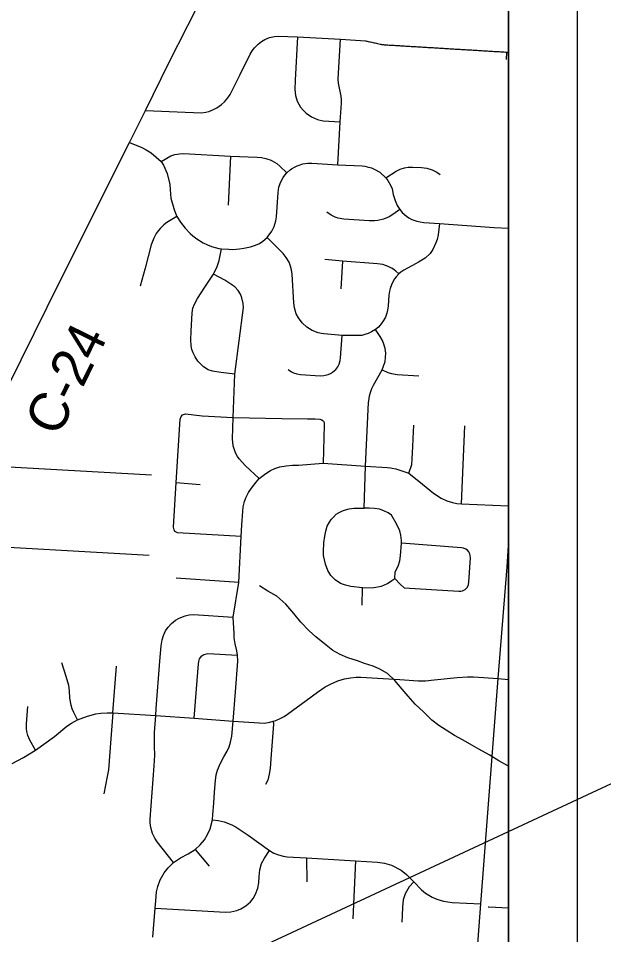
# Model space of a CAD drawing. Extents: x 0 to 34, y 0 to 22.
# Drawn here: x 9.603 to 10.457, y 8.278 to 9.615 of the extents above; entities that cross this region are included whole.
import ezdxf

# ---------------------------------------------------------------- set-up
doc = ezdxf.new("R2010")
doc.units = 0
for name, color, linetype in [('GM_X_Corporation', 7, 'Continuous'), ('GM_X_County_Road', 7, 'Continuous'), ('GM_X_County_Road_Text', 7, 'Continuous'), ('GM_X_Minor_River', 7, 'Continuous'), ('GM_X_Township_Road', 7, 'Continuous'), ('SH_Data', 7, 'Continuous'), ('SH_Text', 7, 'Continuous')]:
    doc.layers.add(name, color=color, linetype=linetype)

msp = doc.modelspace()

# ---------------------------------------------------------------- linework, layer by layer
at = {"layer": 'GM_X_Corporation'}
for points in [[(10.3182, 6.9963), (10.3182, 10.1841), (3.5182, 10.1841)], [(10.3182, 6.9963), (10.3182, 10.1841), (8.0168, 10.1841), (8.012, 10.1113), (7.9906, 9.8037), (7.9854, 9.7171), (7.9173, 8.8475), (7.9043, 8.6471), (7.8824, 8.2446), (7.8769, 8.1664), (7.8619, 7.9568), (7.8248, 7.359), (7.8118, 7.1421)]]:
    msp.add_lwpolyline(points, dxfattribs=at)
at = {"layer": 'GM_X_County_Road'}
for points in [[(9.2983, 8.492), (9.3206, 8.5378), (9.4763, 8.8512), (9.532, 8.9642), (9.6643, 9.2319), (9.7654, 9.4338), (9.7887, 9.4806), (9.823, 9.5499), (9.8784, 9.6595), (9.9012, 9.7059), (9.9498, 9.7963), (10.0655, 10.0271), (10.1462, 10.1841)], [(10.2498, 7.9432), (10.2722, 8.252), (10.2775, 8.3232), (10.3028, 8.6518), (10.3159, 8.8149), (10.3182, 8.8454)], [(10.2884, 8.3191), (10.2894, 8.3191), (10.3182, 8.3175)]]:
    msp.add_lwpolyline(points, dxfattribs=at)
at = {"layer": 'GM_X_Minor_River'}
msp.add_lwpolyline([(10.3182, 8.5241), (10.3181, 8.5242), (10.3037, 8.5321), (10.2897, 8.5408), (10.2749, 8.5488), (10.2643, 8.5548), (10.2518, 8.562), (10.2393, 8.5688), (10.2272, 8.5764), (10.2162, 8.5835), (10.206, 8.5911), (10.1939, 8.6036), (10.1821, 8.6146), (10.1715, 8.6263), (10.1628, 8.6362), (10.1522, 8.649), (10.1416, 8.6593), (10.1306, 8.6657), (10.1208, 8.6702), (10.1083, 8.674), (10.098, 8.6778), (10.084, 8.6823), (10.0727, 8.6872), (10.0621, 8.6929), (10.0522, 8.7004), (10.0371, 8.7129), (10.0272, 8.7213), (10.0155, 8.7341), (10.0053, 8.7466), (9.9935, 8.7606), (9.9803, 8.772), (9.9674, 8.7792), (9.9549, 8.7871)], dxfattribs=at)
at = {"layer": 'GM_X_Township_Road'}
for p, q in [((10.3149, 9.5549), (10.3156, 9.5656)), ((9.9129, 9.4136), (9.9094, 9.3422)), ((10.076, 9.2606), (10.0737, 9.2205)), ((10.2494, 8.9069), (10.2542, 9.0203)), ((9.532, 8.9642), (9.7974, 8.9489)), ((9.8335, 8.9377), (9.8683, 8.935)), ((9.9249, 8.7921), (9.8337, 8.7982)), ((10.1046, 8.7587), (10.1054, 8.7841)), ((9.7414, 8.6018), (9.7468, 8.6699)), ((10.3028, 8.6518), (10.3182, 8.6506)), ((9.8611, 8.4027), (9.8816, 8.3783)), ((10.0233, 8.3902), (10.0239, 8.3552)), ((10.0952, 8.3861), (10.0909, 8.3015))]:
    msp.add_line(p, q, dxfattribs=at)
for points in [[(9.7887, 9.4806), (9.8467, 9.4779), (9.8589, 9.4773), (9.8706, 9.4772), (9.877, 9.4782), (9.881, 9.4792), (9.888, 9.4818), (9.8929, 9.4843), (9.8997, 9.4891), (9.9038, 9.4929), (9.9089, 9.4989), (9.9122, 9.504), (9.916, 9.5114), (9.9262, 9.5318), (9.9416, 9.5626), (9.9443, 9.5673), (9.9475, 9.5717), (9.9509, 9.5754), (9.953, 9.5773), (9.958, 9.5811), (9.9626, 9.5838), (9.9695, 9.5867), (9.9768, 9.5884), (9.9822, 9.589), (10.0104, 9.5877), (10.0729, 9.5843), (10.1094, 9.5819), (10.111, 9.5817), (10.1119, 9.5815), (10.1136, 9.5811), (10.1153, 9.5807), (10.117, 9.5804), (10.1187, 9.58), (10.1204, 9.5796), (10.1221, 9.5792), (10.1238, 9.5789), (10.1255, 9.5785), (10.1272, 9.5781), (10.1289, 9.5777), (10.1307, 9.5773), (10.1314, 9.5772), (10.1321, 9.577), (10.1329, 9.5769), (10.1336, 9.5768), (10.1343, 9.5767), (10.1351, 9.5766), (10.1358, 9.5765), (10.1366, 9.5764), (10.1373, 9.5763), (10.1381, 9.5763), (10.14, 9.5762), (10.1419, 9.5761), (10.1438, 9.5759), (10.1456, 9.5758), (10.1475, 9.5757), (10.1494, 9.5756), (10.1513, 9.5755), (10.1532, 9.5754), (10.1551, 9.5753), (10.157, 9.5752), (10.1589, 9.575), (10.1608, 9.5749), (10.1626, 9.5748), (10.1645, 9.5747), (10.1664, 9.5746), (10.1683, 9.5745), (10.1702, 9.5744), (10.1721, 9.5742), (10.174, 9.5741), (10.1759, 9.574), (10.1778, 9.5739), (10.1796, 9.5738), (10.1815, 9.5737), (10.1834, 9.5736), (10.1853, 9.5734), (10.1872, 9.5733), (10.1891, 9.5732), (10.191, 9.5731), (10.1929, 9.573), (10.1948, 9.5729), (10.1966, 9.5728), (10.1985, 9.5726), (10.2004, 9.5725), (10.2023, 9.5724), (10.2042, 9.5723), (10.2061, 9.5722), (10.208, 9.5721), (10.2099, 9.572), (10.2118, 9.5718), (10.2136, 9.5717), (10.2155, 9.5716), (10.2174, 9.5715), (10.2193, 9.5714), (10.2212, 9.5713), (10.2231, 9.5712), (10.225, 9.5711), (10.2269, 9.5709), (10.2288, 9.5708), (10.2306, 9.5707), (10.2325, 9.5706), (10.2344, 9.5705), (10.2363, 9.5704), (10.2382, 9.5703), (10.2401, 9.5701), (10.242, 9.57), (10.2439, 9.5699), (10.2458, 9.5698), (10.2476, 9.5697), (10.2495, 9.5696), (10.2514, 9.5695), (10.2533, 9.5693), (10.2552, 9.5692), (10.2571, 9.5691), (10.259, 9.569), (10.2609, 9.5689), (10.2627, 9.5688), (10.2646, 9.5687), (10.2665, 9.5685), (10.2684, 9.5684), (10.2703, 9.5683), (10.2722, 9.5682), (10.2741, 9.5681), (10.276, 9.568), (10.2779, 9.5679), (10.2798, 9.5677), (10.2816, 9.5676), (10.2835, 9.5675), (10.2854, 9.5674), (10.2873, 9.5673), (10.2892, 9.5672), (10.2911, 9.5671), (10.293, 9.567), (10.2949, 9.5668), (10.2968, 9.5667), (10.2986, 9.5666), (10.3005, 9.5665), (10.3024, 9.5664), (10.3043, 9.5663), (10.3062, 9.5662), (10.3081, 9.566), (10.31, 9.5659), (10.3119, 9.5658), (10.3138, 9.5657), (10.3156, 9.5656), (10.3166, 9.5655), (10.3176, 9.5655), (10.3182, 9.5655)], [(10.0104, 9.5877), (10.0068, 9.5249), (10.0063, 9.511), (10.0074, 9.5023), (10.0101, 9.494), (10.015, 9.4853), (10.0186, 9.4808), (10.0231, 9.4764), (10.031, 9.471), (10.0394, 9.4674), (10.0476, 9.4656), (10.0727, 9.4638)], [(10.069, 9.4013), (10.0727, 9.4638), (10.0745, 9.4911), (10.0746, 9.4962), (10.0741, 9.5014), (10.0733, 9.506), (10.0711, 9.5153), (10.0701, 9.5205), (10.0697, 9.5256), (10.0701, 9.5347), (10.0729, 9.5843)], [(9.7654, 9.4338), (9.7834, 9.4265), (9.79, 9.4233), (9.797, 9.4187), (9.8119, 9.4061), (9.8153, 9.4006), (9.8206, 9.3885), (9.8241, 9.3724), (9.8253, 9.3583), (9.826, 9.3524), (9.8302, 9.3375), (9.8318, 9.3331), (9.8344, 9.3258), (9.84, 9.3175), (9.8465, 9.3089), (9.854, 9.301), (9.8578, 9.2977), (9.8637, 9.2932), (9.873, 9.2875), (9.8792, 9.2845), (9.8852, 9.2822), (9.8957, 9.2792), (9.8996, 9.2785), (9.9103, 9.278), (9.915, 9.2779), (9.9212, 9.2782), (9.9258, 9.2787), (9.932, 9.2798), (9.9419, 9.2818), (9.949, 9.2839), (9.9551, 9.2866), (9.96, 9.2897), (9.9663, 9.2951), (9.9729, 9.3044), (9.9762, 9.311), (9.9776, 9.3148), (9.9789, 9.3196), (9.9797, 9.3255), (9.9822, 9.3608), (9.9834, 9.3686), (9.9851, 9.374), (9.9871, 9.3785), (9.9896, 9.3828), (9.992, 9.3861), (9.9949, 9.3896), (9.9998, 9.3938), (10.0018, 9.3952), (10.0068, 9.3982), (10.0098, 9.3996), (10.0128, 9.4008), (10.0184, 9.4024), (10.0216, 9.403), (10.0257, 9.4035), (10.0282, 9.4036), (10.0315, 9.4035), (10.069, 9.4013), (10.1048, 9.3995), (10.1088, 9.3991), (10.1121, 9.3985), (10.1185, 9.3967), (10.1223, 9.3951), (10.1302, 9.3906), (10.1393, 9.382), (10.142, 9.3785), (10.1464, 9.3706), (10.1482, 9.366), (10.1501, 9.358), (10.1527, 9.3493), (10.1558, 9.3417), (10.1594, 9.3359), (10.1632, 9.3317), (10.1694, 9.3264), (10.1729, 9.324), (10.1773, 9.3216), (10.1842, 9.319), (10.189, 9.3179), (10.1945, 9.3172), (10.2172, 9.3154), (10.2971, 9.31), (10.3182, 9.3088)], [(9.8119, 9.4061), (9.8256, 9.4143), (9.8317, 9.4162), (9.8386, 9.4173), (9.8441, 9.4175), (9.9129, 9.4136), (9.9518, 9.4122), (9.9578, 9.4118), (9.9643, 9.4106), (9.9674, 9.4096), (9.9705, 9.4085), (9.9735, 9.4071), (9.9771, 9.4052), (9.9805, 9.4029), (9.9849, 9.3992), (9.9949, 9.3896)], [(10.1393, 9.382), (10.1543, 9.392), (10.1603, 9.3948), (10.1666, 9.3968), (10.1715, 9.3976), (10.1781, 9.398), (10.1914, 9.3972), (10.1988, 9.3962), (10.2067, 9.3937), (10.2134, 9.3904), (10.2182, 9.387)], [(10.1594, 9.3359), (10.1496, 9.3287), (10.1438, 9.3253), (10.1359, 9.322), (10.1275, 9.3199), (10.1228, 9.3194), (10.1151, 9.3193), (10.078, 9.3219), (10.0699, 9.3234), (10.0653, 9.325), (10.0594, 9.3279), (10.0533, 9.3321)], [(9.8344, 9.3258), (9.8199, 9.317), (9.8155, 9.3136), (9.81, 9.3083), (9.8057, 9.303), (9.8045, 9.3009), (9.8008, 9.2942), (9.7989, 9.2895), (9.7973, 9.2845), (9.7882, 9.2504), (9.7813, 9.2241)], [(10.2172, 9.3154), (10.2153, 9.2991), (10.2138, 9.2922), (10.2122, 9.2875), (10.2077, 9.2779), (10.2038, 9.2721), (10.1965, 9.2651), (10.1867, 9.259), (10.1832, 9.2572), (10.1709, 9.2505), (10.1655, 9.2474), (10.1612, 9.2446), (10.1579, 9.242), (10.154, 9.2377), (10.152, 9.235), (10.1498, 9.2315), (10.1472, 9.2264), (10.1453, 9.2209), (10.1443, 9.2169), (10.1436, 9.2111), (10.1425, 9.1951), (10.1417, 9.1894), (10.1405, 9.1846), (10.1385, 9.1792), (10.1359, 9.1741), (10.1326, 9.1694), (10.1283, 9.1646), (10.1241, 9.161), (10.1185, 9.1574), (10.1134, 9.155), (10.1088, 9.1535), (10.104, 9.1524), (10.0756, 9.1522), (10.049, 9.1547), (10.0452, 9.1552), (10.0404, 9.1563), (10.0318, 9.1596), (10.024, 9.1644), (10.0172, 9.1707), (10.0118, 9.178), (10.0087, 9.1839), (10.0059, 9.1926), (10.0049, 9.1999), (10.0026, 9.2416), (10.0018, 9.2479), (10.0003, 9.2535), (9.9981, 9.2591), (9.9941, 9.266), (9.9893, 9.2718), (9.9663, 9.2951)], [(9.919, 9.0958), (9.8985, 9.0984), (9.8866, 9.1), (9.8803, 9.1022), (9.8732, 9.1066), (9.8653, 9.1148), (9.8611, 9.1213), (9.8582, 9.1272), (9.8562, 9.1316), (9.8552, 9.1374), (9.8547, 9.1461), (9.8554, 9.1587), (9.8568, 9.1854), (9.8579, 9.1922), (9.8601, 9.1982), (9.8648, 9.206), (9.8755, 9.2227), (9.8878, 9.2419), (9.8932, 9.2531), (9.896, 9.2615), (9.8996, 9.2785)], [(10.1579, 9.242), (10.1538, 9.2459), (10.1512, 9.248), (10.1478, 9.2503), (10.1463, 9.2511), (10.1427, 9.253), (10.1388, 9.2545), (10.1349, 9.2557), (10.1309, 9.2565), (10.1268, 9.257), (10.076, 9.2606), (10.0502, 9.263)], [(9.9547, 8.9439), (9.9347, 8.9624), (9.9256, 8.9722), (9.9229, 8.9756), (9.9198, 8.981), (9.9168, 8.9915), (9.9159, 9.0014), (9.9164, 9.0327), (9.919, 9.0958), (9.9316, 9.193), (9.931, 9.1991), (9.9292, 9.2073), (9.9274, 9.2127), (9.924, 9.2178), (9.9192, 9.2232), (9.9046, 9.2329), (9.8878, 9.2419)], [(10.1076, 8.9006), (10.1094, 8.9617), (10.1141, 9.0543), (10.1148, 9.06), (10.1155, 9.0641), (10.1169, 9.0692), (10.119, 9.075), (10.1213, 9.08), (10.1337, 9.1024), (10.136, 9.1075), (10.1381, 9.1145), (10.1389, 9.1202), (10.139, 9.1267), (10.1382, 9.1332), (10.1365, 9.1395), (10.1343, 9.1449), (10.131, 9.1506), (10.1241, 9.161)], [(9.9967, 9.1027), (10.0017, 9.0993), (10.0048, 9.0979), (10.0095, 9.0964), (10.0149, 9.0955), (10.0433, 9.0936), (10.0488, 9.0938), (10.0551, 9.0953), (10.0583, 9.0967), (10.0616, 9.0988), (10.0661, 9.1027), (10.0691, 9.1066), (10.0711, 9.1105), (10.0727, 9.1157), (10.0733, 9.1195), (10.0756, 9.1522)], [(10.1337, 9.1024), (10.1421, 9.0983), (10.1476, 9.0966), (10.1556, 9.0954), (10.1871, 9.0933)], [(9.9284, 8.8593), (9.8357, 8.8645), (9.8337, 8.8653), (9.8318, 8.8665), (9.8304, 8.869), (9.8299, 8.8726), (9.8335, 8.9377), (9.8396, 9.0301), (9.8408, 9.0341), (9.8428, 9.0364), (9.847, 9.0378), (9.8715, 9.0351), (9.9164, 9.0327)], [(9.9164, 9.0327), (9.9876, 9.0312), (10.025, 9.0309), (10.0362, 9.0307), (10.0428, 9.0301), (10.0461, 9.0292), (10.0484, 9.0272), (10.0491, 9.0252), (10.0492, 9.0213), (10.048, 8.9659)], [(10.1726, 8.9515), (10.177, 8.9642), (10.1777, 8.972), (10.1781, 8.982), (10.1787, 8.9892), (10.179, 9.002), (10.1798, 9.0213)], [(9.7996, 8.2748), (9.8029, 8.3168), (9.8038, 8.3277), (9.805, 8.341), (9.8066, 8.3484), (9.8104, 8.3585), (9.816, 8.3684), (9.8219, 8.3759), (9.8299, 8.3836), (9.84, 8.3905), (9.8509, 8.3962), (9.8611, 8.4027), (9.8683, 8.4092), (9.8747, 8.4169), (9.8794, 8.4245), (9.883, 8.4326), (9.8864, 8.4458), (9.887, 8.4538), (9.8883, 8.4703), (9.8894, 8.4861), (9.8907, 8.503), (9.8919, 8.5117), (9.8936, 8.5181), (9.8976, 8.5275), (9.9032, 8.5378), (9.908, 8.5462), (9.9107, 8.5525), (9.9128, 8.5592), (9.9146, 8.5677), (9.9164, 8.5899), (9.9198, 8.6324), (9.9233, 8.6774), (9.9231, 8.6861), (9.9222, 8.6924), (9.9197, 8.7026), (9.9183, 8.7111), (9.9183, 8.7178), (9.9165, 8.7414), (9.9249, 8.7921), (9.9284, 8.8593), (9.9293, 8.8759), (9.9307, 8.8957), (9.9314, 8.9025), (9.9333, 8.9102), (9.9351, 8.9153), (9.939, 8.9233), (9.9432, 8.9297), (9.9484, 8.9361), (9.9547, 8.9439), (9.9641, 8.9512), (9.9709, 8.9554), (9.9774, 8.9584), (9.9849, 8.9606), (9.994, 8.962), (10.0029, 8.9629), (10.012, 8.963), (10.048, 8.9659), (10.1094, 8.9617), (10.1409, 8.9596), (10.1458, 8.9591), (10.1484, 8.9587), (10.1537, 8.9576), (10.1626, 8.9549), (10.1726, 8.9515), (10.1928, 8.9354), (10.2087, 8.9223), (10.2196, 8.9151), (10.2279, 8.9113), (10.2365, 8.9086), (10.2428, 8.9073), (10.2494, 8.9069), (10.3182, 8.9036)], [(10.1054, 8.7841), (10.0883, 8.786), (10.0804, 8.7879), (10.073, 8.7907), (10.0651, 8.7961), (10.0592, 8.8024), (10.0545, 8.8094), (10.051, 8.8186), (10.0496, 8.8249), (10.0485, 8.8315), (10.0483, 8.8372), (10.0488, 8.8497), (10.0502, 8.8595), (10.0515, 8.8671), (10.0539, 8.8743), (10.057, 8.8799), (10.0596, 8.8841), (10.0627, 8.8875), (10.0669, 8.8915), (10.0711, 8.8943), (10.0758, 8.8966), (10.0802, 8.8981), (10.0858, 8.8993), (10.0925, 8.9005), (10.1076, 8.9006)], [(10.1054, 8.7841), (10.1215, 8.7847), (10.1328, 8.7868), (10.1414, 8.7905), (10.1479, 8.7947), (10.1523, 8.7979), (10.1528, 8.8077), (10.1571, 8.8156), (10.1596, 8.8234), (10.1606, 8.8307), (10.1618, 8.8494), (10.1619, 8.8535), (10.1611, 8.8608), (10.1595, 8.8672), (10.1545, 8.8776), (10.1472, 8.8903), (10.1428, 8.8938), (10.1363, 8.8966), (10.1298, 8.8989), (10.1228, 8.9), (10.115, 8.9005), (10.1076, 8.9006)], [(9.4763, 8.8512), (9.4863, 8.8499), (9.5034, 8.8486), (9.794, 8.8317)], [(10.1523, 8.7979), (10.1603, 8.7896), (10.1657, 8.7843), (10.2454, 8.7792), (10.2484, 8.7793), (10.251, 8.78), (10.2547, 8.7819), (10.258, 8.7854), (10.2597, 8.7889), (10.2604, 8.7923), (10.2626, 8.8278), (10.2618, 8.8336), (10.2601, 8.8368), (10.2581, 8.839), (10.2558, 8.8408), (10.2526, 8.8421), (10.2495, 8.8427), (10.1618, 8.8494)], [(9.8299, 8.3836), (9.8059, 8.4139), (9.8023, 8.4192), (9.799, 8.4259), (9.7964, 8.4348), (9.7957, 8.4414), (9.7958, 8.4466), (9.8016, 8.5244), (9.8026, 8.5403), (9.8022, 8.553), (9.8019, 8.5659), (9.8022, 8.5731), (9.8041, 8.5979), (9.8042, 8.6081), (9.8099, 8.6773), (9.8117, 8.6995), (9.813, 8.7082), (9.815, 8.7149), (9.8181, 8.7213), (9.8218, 8.7268), (9.8268, 8.7323), (9.8326, 8.7369), (9.838, 8.7401), (9.8468, 8.7435), (9.8525, 8.7446), (9.8587, 8.7451), (9.9165, 8.7414)], [(9.8598, 8.594), (9.8661, 8.6733), (9.8664, 8.677), (9.8677, 8.6808), (9.8708, 8.6848), (9.8741, 8.6871), (9.8796, 8.6885), (9.9231, 8.6861)], [(9.6897, 8.5915), (9.6844, 8.6022), (9.6821, 8.6076), (9.6803, 8.6133), (9.6787, 8.6231), (9.6779, 8.6345), (9.6771, 8.6417), (9.6734, 8.6549), (9.667, 8.6748)], [(9.5947, 8.5279), (9.611, 8.5367), (9.6287, 8.5475), (9.6561, 8.5672), (9.6744, 8.5823), (9.6812, 8.5868), (9.6897, 8.5915), (9.7041, 8.5971), (9.7166, 8.6003), (9.7238, 8.6014), (9.7329, 8.602), (9.7414, 8.6018), (9.8041, 8.5979), (9.8598, 8.594), (9.9164, 8.5899), (9.9625, 8.587), (9.97, 8.5882), (9.9751, 8.5896), (9.9789, 8.5909), (9.985, 8.5935), (9.9908, 8.5967), (9.9958, 8.6001), (10.023, 8.6198), (10.0398, 8.6319), (10.0509, 8.6396), (10.0596, 8.6444), (10.0694, 8.6485), (10.0789, 8.6513), (10.0878, 8.653), (10.096, 8.6538), (10.1026, 8.6539), (10.1598, 8.6505), (10.1863, 8.6488), (10.1972, 8.6488), (10.2097, 8.6499), (10.2432, 8.6532), (10.2581, 8.6545), (10.2672, 8.6546), (10.3028, 8.6518)], [(9.6287, 8.5475), (9.6201, 8.5621), (9.6175, 8.5687), (9.6161, 8.5745), (9.6156, 8.5787), (9.6153, 8.586), (9.6175, 8.6113)], [(9.7414, 8.6018), (9.7385, 8.5642), (9.7348, 8.5186), (9.7331, 8.5089), (9.7279, 8.4839)], [(9.9751, 8.5896), (9.9756, 8.5856), (9.9716, 8.535), (9.9705, 8.5206), (9.9691, 8.5123), (9.9674, 8.5037), (9.9638, 8.4973)], [(9.8864, 8.4458), (9.8946, 8.4447), (9.9037, 8.4427), (9.9146, 8.4386), (9.9212, 8.4352), (9.9386, 8.4233), (9.9695, 8.4011), (9.9759, 8.3974), (9.9811, 8.3951), (9.9895, 8.3927), (9.9953, 8.3918), (10.0233, 8.3902), (10.0952, 8.3861), (10.1268, 8.3843), (10.1373, 8.3827), (10.1473, 8.3797), (10.1616, 8.3722), (10.1694, 8.366), (10.1798, 8.3554), (10.1913, 8.3437), (10.1971, 8.339), (10.2067, 8.3331), (10.2135, 8.3301), (10.223, 8.3271), (10.2358, 8.3253), (10.2775, 8.3232)], [(9.8029, 8.3168), (9.9056, 8.3112), (9.9134, 8.3116), (9.9222, 8.3137), (9.928, 8.3161), (9.935, 8.3204), (9.9417, 8.3264), (9.9456, 8.3312), (9.9494, 8.3376), (9.9527, 8.346), (9.9541, 8.3541), (9.9547, 8.3633), (9.9555, 8.3727), (9.9581, 8.382), (9.9621, 8.3901), (9.9695, 8.4011)], [(10.1798, 8.3554), (10.173, 8.3479), (10.1673, 8.3379), (10.1646, 8.3292), (10.1634, 8.3183), (10.1632, 8.3062), (10.1627, 8.2965)], [(10.2884, 8.3191), (10.2894, 8.3191), (10.3182, 8.3175)]]:
    msp.add_lwpolyline(points, dxfattribs=at)
at = {"layer": 'SH_Data'}
for p, q in [((10.4182, 10.2841), (10.4182, 3.2841)), ((10.3182, 10.1841), (10.3182, 3.3841))]:
    msp.add_line(p, q, dxfattribs=at)
at = {"layer": 'SH_Text'}
msp.add_lwpolyline([(10.7687, 8.6388), (6.7687, 6.7736), (10.7687, 8.1004)], close=True, dxfattribs=at)

# ---------------------------------------------------------------- texts
at = {"layer": 'GM_X_County_Road_Text'}
msp.add_text('C-24', height=0.05682, rotation=63.7423, dxfattribs=at).set_placement((9.6615, 9.0027))

doc.saveas('drawing.dxf')
